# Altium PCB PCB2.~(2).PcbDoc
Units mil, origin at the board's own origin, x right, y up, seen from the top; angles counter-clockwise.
Board outline 6000 x 4000 mil, 2 copper layers (Top Layer, Bottom Layer); 14 components, 16 nets, 44 pads, 0 vias.
Unrouted connection lines stored in the file: 22.
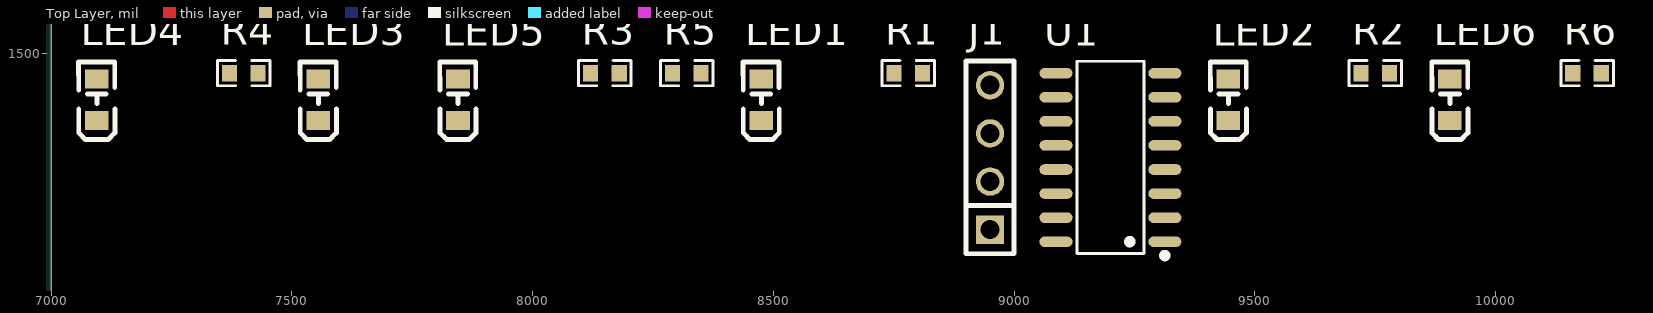
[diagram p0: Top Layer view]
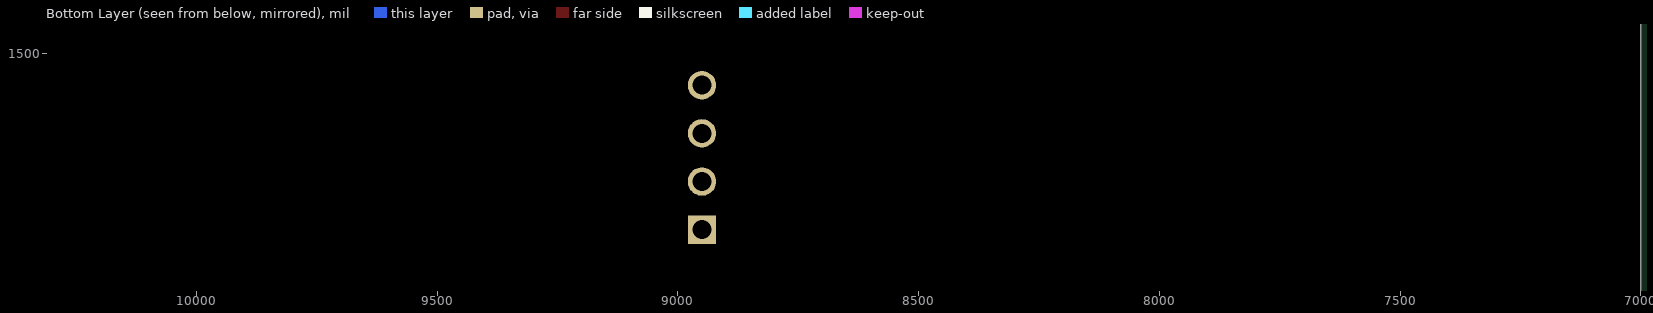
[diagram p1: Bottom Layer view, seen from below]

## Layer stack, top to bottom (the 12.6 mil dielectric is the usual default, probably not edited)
Top Solder: solder mask 0.4, Solder Resist, Dk 3.5
Top Layer: signal copper 1.4
Dielectric 1: dielectric 12.6, FR-4, Dk 4.8
Bottom Layer: signal copper 1.4
Bottom Solder: solder mask 0.4, Solder Resist, Dk 3.5

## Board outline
1000,1000 7000,1000 7000,5000 1000,5000

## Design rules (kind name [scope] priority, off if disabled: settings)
Clearance [All] p1: gap=10 ignorepadtopadclearanceinfootprint=FALSE except(0: Arc-Hole Track-Hole SMDPad-Hole THPad-Hole Via-Hole Fill-Hole Poly-Hole Region-Hole Text-Hole)
PolygonConnect [All] p1: connectstyle=Relief reliefconductorwidth=10 reliefentries=4 polygonreliefangle="90 Angle" airgapwidth=10
RoutingVias [All] p1: holewidth=28 width=50 viastyle="Through Hole" minholewidth=28 minwidth=50 maxholewidth=28 maxwidth=50
SolderMaskExpansion [All] p1: expansion=4 istentingtop=FALSE
Width [All] p1: maxlimit=10 minlimit=10 preferedwidth=10
30 further rules are at their usual default settings.

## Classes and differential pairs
component class Sheet1: J1 LED1 LED2 LED4 LED5 R1 R2 R3 R4 R5 U1

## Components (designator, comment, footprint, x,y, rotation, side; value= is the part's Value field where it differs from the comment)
J1 "CON4" SIP4 8950,1135 r90 top
LED1 "XL-2012SURC" LED0805-RD_RED 8475,1405 r90 top
LED2 "XL-2012SURC" LED0805-RD_RED 9445,1405 r90 top
LED3 "XL-2012SURC" LED0805-RD_RED 7555,1405 r90 top
LED4 "XL-2012SURC" LED0805-RD_RED 7095,1405 r90 top
LED5 "XL-2012SURC" LED0805-RD_RED 7845,1405 r90 top
LED6 "XL-2012SURC" LED0805-RD_RED 9905,1405 r90 top
R1 "220Ω" R0603 8780,1460 r0 top
R2 "220Ω" R0603 9750,1460 r0 top
R3 "220Ω" R0603 8150,1460 r0 top
R4 "220Ω" R0603 7400,1460 r0 top
R5 "220Ω" R0603 8320,1460 r0 top
R6 "220Ω" R0603 10190,1460 r0 top
U1 "HEF4017BT,653" SOP-16_L10.0-W3.9-P1.27-LS6.0-BL 9200,1285 r90 top

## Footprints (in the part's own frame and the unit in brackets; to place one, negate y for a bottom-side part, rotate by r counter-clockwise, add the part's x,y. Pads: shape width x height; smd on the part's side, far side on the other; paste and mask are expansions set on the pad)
LED0805-RD_RED [mm]
  rect 1x1.25 smd: 1(-1.1,0) 2(1.1,0)
  silkscreen extent -2.1,-0.95 1.98,0.96
R0603 [mil]
  rect 31.75x34.02 smd: 1(-29.66,0) 2(29.66,0)
  silkscreen extent -55,-26 55,26
SIP4 [mm]
  rect 1.5x1.5 hole 1: 1(0,0)
  round 1.5 hole 1: 2(2.54,0) 3(5.08,0) 4(7.62,0)
  silkscreen extent -1.27,-1.27 8.89,1.27
SOP-16_L10.0-W3.9-P1.27-LS6.0-BL [mm]
  oval 0.56x1.745 smd: 1(-4.445,-2.872) 2(-3.175,-2.872) 3(-1.905,-2.872) 4(-0.635,-2.872) 5(0.635,-2.872) 6(1.905,-2.872) 7(3.175,-2.872) 8(4.445,-2.872) 9(4.445,2.872) 10(3.175,2.872) 11(1.905,2.872) 12(0.635,2.872) 13(-0.635,2.872) 14(-1.905,2.872) 15(-3.175,2.872) 16(-4.445,2.872)
  silkscreen extent -5.33,-3.02 5.08,1.77

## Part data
J1: "Connector"
LED1 LED2 LED3 LED4 LED5 LED6: Color Temperature=-, Emitted Color=红色, Forward Current=25mA, JLCPCB Part Class=扩展库, Lens Color=无色透明透镜, Manufacturer=XINGLIGHT(成兴光), Operating Temperature=-30℃~+85℃, Power Dissipation=55mW
R1 R2 R3 R4 R5 R6: library part 0603WAF2200T5E, JLCPCB Part Class=基础库, LCSC Part Name="220Ω ±1% 100mW 厚膜电阻", Manufacturer=UNI-ROYAL(厚声), Operating Temperature Range=-55℃~+155℃, Overload Voltage (Max)=75V, Power(Watts)=100mW, Temperature Coefficient=±100ppm/℃, Tolerance=±1%
U1: JLCPCB Part Class=扩展库, LCSC Part Name="30MHz 10位十进制计数器", Manufacturer=Nexperia(安世), Operating Temperature=-40℃~+85℃, Voltage - Supply=4.5V~15.5V

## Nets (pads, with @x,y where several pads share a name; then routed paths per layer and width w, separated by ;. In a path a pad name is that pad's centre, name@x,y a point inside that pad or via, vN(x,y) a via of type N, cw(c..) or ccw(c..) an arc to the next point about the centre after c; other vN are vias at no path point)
+5V: J1.1 U1.16
CLK: J1.4 U1.14
GND: J1.2 LED1.1 LED2.1 LED3.1 LED4.1 LED5.1 LED6.1 U1.8
NetLED1_2: LED1.2 R1.1
NetLED2_2: LED2.2 R2.1
NetLED3_2: LED3.2 R3.1
NetLED4_2: LED4.2 R4.1
NetLED5_2: LED5.2 R5.2
NetLED6_2: LED6.2 R6.1
NetR1_2: R1.2 U1.3
NetR2_2: R2.2 U1.2
NetR3_2: R3.2 U1.4
NetR4_2: R4.2 U1.7
NetR5_1: R5.1 U1.10
NetR6_2: R6.2 U1.1
RST: J1.3 U1.15
pads on no net: U1.5 U1.6 U1.9 U1.11 U1.12 U1.13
